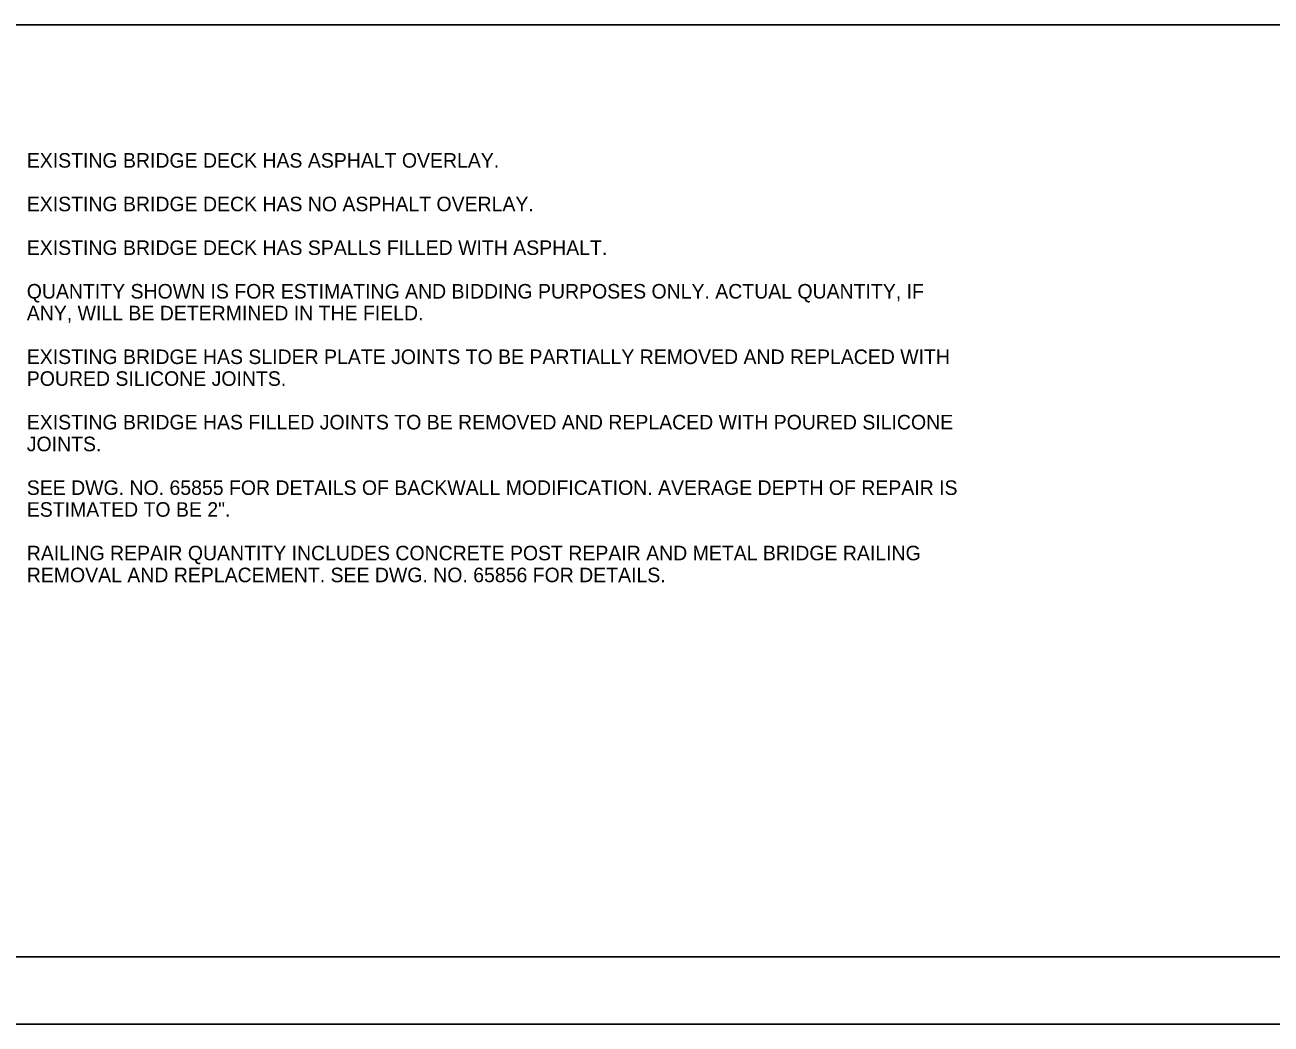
# Model space of a CAD drawing. Extents: x 18 to 14744716, y -5 to 1829144.
# Drawn here: x 30.4 to 41.09, y -5.37 to 3.2 of the extents above; entities that cross this region are included whole.
import ezdxf

# ---------------------------------------------------------------- set-up
doc = ezdxf.new("R2010")
doc.units = 0
for name, color, linetype in [('B_Text', 7, 'Continuous'), ('R_Border', 7, 'Continuous'), ('R_No Plot', 7, 'Continuous')]:
    doc.layers.add(name, color=color, linetype=linetype)

msp = doc.modelspace()

# ---------------------------------------------------------------- linework, layer by layer
at = {"layer": 'B_Text'}
msp.add_line((19.392, 3.201), (51.101, 3.201), dxfattribs=at)
at = {"layer": 'R_Border'}
msp.add_line((51.2, -4.796), (19.293, -4.796), dxfattribs=at)
at = {"layer": 'R_No Plot'}
msp.add_lwpolyline([(17.777, 16.628), (51.777, 16.628), (51.777, -5.372), (17.777, -5.372)], close=True, dxfattribs=at)

# ---------------------------------------------------------------- texts
at = {"layer": 'B_Text'}
for s, p in [('EXISTING BRIDGE DECK HAS ASPHALT OVERLAY.', (30.412, 1.976)), ('EXISTING BRIDGE DECK HAS NO ASPHALT OVERLAY.', (30.412, 1.602)), ('EXISTING BRIDGE DECK HAS SPALLS FILLED WITH ASPHALT.', (30.412, 1.227)), ('QUANTITY SHOWN IS FOR ESTIMATING AND BIDDING PURPOSES ONLY. ACTUAL QUANTITY, IF ', (30.412, 0.853)), ('ANY, WILL BE DETERMINED IN THE FIELD.', (30.412, 0.666)), ('EXISTING BRIDGE HAS SLIDER PLATE JOINTS TO BE PARTIALLY REMOVED AND REPLACED WITH ', (30.412, 0.291)), ('POURED SILICONE JOINTS.', (30.412, 0.104)), ('EXISTING BRIDGE HAS FILLED JOINTS TO BE REMOVED AND REPLACED WITH POURED SILICONE ', (30.412, -0.27)), ('JOINTS.', (30.412, -0.457)), ('SEE DWG. NO. 65855 FOR DETAILS OF BACKWALL MODIFICATION. AVERAGE DEPTH OF REPAIR IS ', (30.412, -0.832)), ('ESTIMATED TO BE 2".', (30.412, -1.019)), ('RAILING REPAIR QUANTITY INCLUDES CONCRETE POST REPAIR AND METAL BRIDGE RAILING ', (30.412, -1.393)), ('REMOVAL AND REPLACEMENT. SEE DWG. NO. 65856 FOR DETAILS.', (30.412, -1.581))]:
    msp.add_text(s, height=0.1248, dxfattribs=at).set_placement(p)

doc.saveas('drawing.dxf')
